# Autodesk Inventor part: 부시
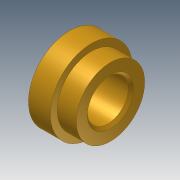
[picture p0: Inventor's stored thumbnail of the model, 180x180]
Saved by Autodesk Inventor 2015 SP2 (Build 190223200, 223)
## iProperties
Created: 2011-04
Part Number: 부시
Document SubType Name: Modeling
Designer: 한국산업디자인학원 [http://gmhk.co.kr]
Density: 1 g/cm^3
Material: 일반
Appearance: 황동 - 새틴
Author: pww
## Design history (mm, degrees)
sketch "스케치1"
  geometry: L1 (0, 0)-(15, 0); L2 (0, 6)-(15, 6); L3 (15, 6)-(15, 12.5); L4 (15, 12.5)-(8, 12.5); L5 (8, 12.5)-(8, 15); L6 (8, 15)-(0, 15); L7 (0, 15)-(0, 6)
  constraints: 14 end point, 4 parallel, 2 vertical alignment, 1 horizontal, 1 perpendicular, 1 vertical
  dimensions: "d0" = 15 distance of L1.start L1.end; "d1" = 12 diameter of L2 L1; "d2" = 25 diameter of L4 L1; "d3" = 8 distance of L5.end L6.end; "d4" = 30 diameter of L6 L1
revolve "회전1" sketch "스케치1" stored, may be unused: angle "d5" = 90 deg
chamfer "모따기1" distance "d6" = 1; stored, may be unused: second distance "d7" = 2, angle "d8" = 45 deg
node "솔리드1"
